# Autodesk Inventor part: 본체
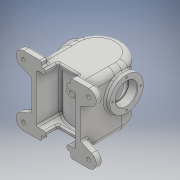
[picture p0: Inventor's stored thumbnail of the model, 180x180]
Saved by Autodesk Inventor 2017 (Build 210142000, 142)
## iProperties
Part Number: 본체
Material: 일반
Document SubType Name: Modeling
Designer: user
Density: 1 g/cm^3
Appearance: 기본값
Mass: 512.747 g
Surface Area: 1155.08 cm^2
Volume: 512.747 cm^3
Author: user
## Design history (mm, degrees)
sketch "스케치2"
  geometry: L1 (76, 0)-(76, -114); L2 (76, 0)-(121, 0); L3 (121, 0)-(121, -108); L4 (121, -108)-(104.5, -108); L5 (104.5, -108)-(104.5, -114); L6 (104.5, -114)-(92.5, -114); L7 (76, -9)-(112, -9); L8 (112, -9)-(112, -99); L9 (112, -99)-(92.5, -99); L10 (92.5, -99)-(92.5, -114); L11 (92.5, -114)-(76, -114); L12 (76, 0)-(76, -9); 1 further point
  constraints: 24 end point, 9 perpendicular, 2 horizontal, 1 collinear, 1 point on line, 1 vertical
  dimensions: "d3" = 76 distance from line of point (0, 0) L1; "d4" = 90 diameter of L3 L1; "d5" = 114 distance of L1.start L1.end; "d6" = 108 distance between parallel lines of L2 L4; "d7" = 57 diameter of L5 L1; "d8" = 0 distance from line of point (0, 0) L2; "d9" = 9 distance between parallel lines of L4 L9; "d10" = 9 distance between parallel lines of L2 L7; "d11" = 9 distance between parallel lines of L8 L3; "d12" = 33 diameter of L10 L1
revolve "회전1" sketch "스케치2" stored, may be unused: angle "d13" = 90 deg
node "작업 평면1"
sketch "스케치4"
  geometry: L1 (47.5, -114)-(104.5, -114) reference; C1 r 31 at (76, -40); 1 further point
  constraints: 1 centre point
  dimensions: "d15" = 62 diameter of C1; "d16" = 74 distance from line of L1 C1.centre; "d17" = 76 horizontal distance of point (0, 0) C1.centre
extrude "돌출1" join sketch "스케치4" stored distance "d18" = 10; taper "d19" = 0 deg
hole "구멍1" diameter "d22" = 35; stored, may be unused: countersink angle "d26" = 90 deg, drill point angle "d28" = 0 deg; dims "d20" = 10, "d21" = 10, "d23" = 6, "d24" = 40, "d25" = 16, "d27" = 8
node "작업 평면2"
sketch "스케치5"
  geometry: L1 (-28.5, -114)-(28.5, -114) reference; C1 r 7.5 at (0, -40); 1 further point
  constraints: 1 centre point, 1 vertical alignment
  dimensions: "d30" = 15 diameter of C1; "d31" = 74 distance from line of C1.centre L1
extrude "돌출2" join sketch "스케치5" stored distance "d32" = 10; taper "d33" = 0 deg
node "작업 평면3"
hole "구멍2" diameter "d37" = 5.188; stored, may be unused: countersink angle "d41" = 90 deg, drill point angle "d43" = 118 deg; dims "d35" = 10, "d36" = 10, "d38" = 12, "d39" = 40, "d40" = 16, "d42" = 16
sketch "스케치10" dims "d56" = 10, "d60" = 10
  geometry: L1 (74, 10)-(-74, 10); L2 (-74, 10)-(-74, -118); L3 (-74, -118)-(74, -118); L4 (74, -118)-(74, 10); L5 (-45, 0)-(45, 0) reference; L6 (60, 10)-(-60, 10); L7 (60, -118)-(-60, -118); L8 (74, -4)-(74, -104); L9 (-74, -4)-(-74, -104); A1 r 14 centre (60, -4) between (60, 10) and (74, -4); A2 r 14 centre (-60, -4) between (-60, 10) and (-74, -4); A3 r 14 centre (60, -104) between (60, -118) and (74, -104); A4 r 14 centre (-60, -104) between (-60, -118) and (-74, -104); 1 further point
  constraints: 16 end point, 8 point on circle, 8 point on line, 4 centre point, 2 horizontal, 2 parallel, 1 perpendicular, 1 vertical, 6 other
  dimensions: "d44" = 128 distance between parallel lines of L3 L1; "d45" = 148 distance of L1.start L1.end; "d46" = 74 distance from line of point (0, 0) L4; "d47" = 10 distance between parallel lines of L5 L1; "d48" = 28 diameter of A1; "d49" = 60 horizontal distance of point (0, 0) A1.centre; "d50" = 14 distance from line of L1 A1.centre; "d53" = 120 distance of A1.centre A2.centre; "d63" = 100 distance of A1.centre A3.centre
extrude "돌출3" join sketch "스케치10" distance "d65" = 12; taper "d66" = 0 deg
sketch "스케치13"
  geometry: L1 (74, 104)-(74, 4) reference; L2 (60, -10)-(-60, -10) reference; L3 (-74, 4)-(-74, 104) reference; L4 (-60, 118)-(60, 118) reference; L5 (-45, 0)-(45, 0); L6 (45, 0)-(45, 108); L7 (45, 108)-(-45, 108); L8 (-45, 108)-(-45, 0); L9 (-36, 9)-(36, 9); L10 (36, 9)-(36, 99); L11 (36, 99)-(-36, 99); L12 (-36, 99)-(-36, 9); A1 r 14 centre (60, 4) between (60, -10) and (74, 4) reference; A2 r 14 centre (-60, 4) between (-74, 4) and (-60, -10) reference; A3 r 14 centre (-60, 104) between (-60, 118) and (-74, 104) reference; A4 r 14 centre (60, 104) between (74, 104) and (60, 118) reference; 1 further point
  constraints: 16 end point, 4 parallel, 2 perpendicular, 1 horizontal, 3 other
  dimensions: "d67" = 10 distance between parallel lines of L2 L5; "d68" = 45 distance from line of point (0, 0) L8; "d69" = 45 distance from line of L6 point (0, 0); "d70" = 10 distance between parallel lines of L4 L7; "d71" = 9 distance between parallel lines of L8 L12
  node "절단 모서리 투영2"
extrude "돌출4" join sketch "스케치13" stored distance "d72" = 12; taper "d73" = 0 deg
sketch "스케치14"
  geometry: L1 (-78, -64)-(50, -64) reference; L2 (50, -64)-(50, -76) reference; L3 (50, -76)-(-78, -76) reference; L4 (-78, -76)-(-78, -64) reference; C1 r 31 at (0, 0) reference; C2 r 20 at (0, 0) reference; 1 further point
hole "구멍3" sketch "스케치14" at (0, 0) diameter "d74" = 40; stored, may be unused: countersink angle "d78" = 90 deg, drill point angle "d80" = 0 deg; dims "d75" = 12, "d76" = 40, "d77" = 16, "d79" = 16
extrude "돌출5" cut sketch "스케치13" stored distance "d81" = 12; taper "d82" = 0 deg
fillet "모깎기1" dims "d83" = 12
sketch "스케치15"
  geometry: L1 (40, -23)-(80, -23); L2 (80, -23)-(80, 23); L3 (80, 23)-(40, 23); L4 (40, 23)-(40, -23); L5 (40, -23)-(80, 23); L6 (80, -23)-(40, 23); L7 (0, 0)-(120, 0) reference; 1 further point
  constraints: 12 end point, 2 midpoint, 2 parallel, 1 horizontal, 1 perpendicular
  dimensions: "d84" = 23 distance between parallel lines of L3 L7; "d85" = 40 distance of L1.start L1.end
extrude "돌출6" cut sketch "스케치15" stored distance "d86" = 12; taper "d87" = 0 deg
sketch "스케치16"
  geometry: L1 (80, 0)-(80, 12) reference; L2 (80, 12)-(120, 12) reference; L3 (120, 0)-(120, 12) reference; L4 (120, 0)-(80, 0) reference; L5 (40, 12)-(40, 0) reference; L6 (40, 0)-(0, 0) reference; L7 (0, 0)-(0, 12) reference; L8 (0, 12)-(40, 12) reference; L9 (33, -12)-(87, -12); L10 (87, -12)-(87, 12); L11 (87, 12)-(33, 12); L12 (33, 12)-(33, -12); L13 (33, -12)-(87, 12); L14 (87, -12)-(33, 12); L15 (15, 76)-(15, 12) reference; 1 further point
  constraints: 12 end point, 2 midpoint, 2 parallel, 1 horizontal, 1 perpendicular
  dimensions: "d88" = 12 distance from line of point (60, 0) L11; "d89" = 18 distance between parallel lines of L15 L12
extrude "돌출7" cut sketch "스케치16" stored distance "d90" = 12; taper "d91" = 0 deg
sketch "스케치17"
  geometry: L1 (-87, -12)-(-33, -12); L2 (-33, -12)-(-33, 12); L3 (-33, 12)-(-87, 12); L4 (-87, 12)-(-87, -12); L5 (-87, -12)-(-33, 12); L6 (-33, -12)-(-87, 12); L7 (-105, 62.696)-(-105, 12) reference; 1 further point
  constraints: 12 end point, 2 midpoint, 2 parallel, 1 horizontal, 1 perpendicular
  dimensions: "d92" = 12 distance from line of point (-60, 0) L3; "d93" = 18 distance between parallel lines of L7 L4
extrude "돌출8" cut sketch "스케치17" stored distance "d94" = 12; taper "d95" = 0 deg
sketch "스케치18"
  geometry: L1 (-33, 108)-(-27, 108) reference; L2 (-27, 118)-(-27, 108) reference; L3 (-60, 118)-(-27, 118) reference; L4 (-74, 4)-(-74, 104) reference; L5 (-27, -10)-(-60, -10) reference; L6 (-27, 0)-(-27, -10) reference; L7 (-20, 0)-(-27, 0) reference; L8 (-20, 9)-(-20, 0) reference; L9 (-36, 9)-(-20, 9) reference; L10 (-36, 99)-(-36, 9) reference; L11 (-20, 99)-(-36, 99) reference; L12 (-20, 108)-(-20, 99) reference; L13 (-27, 108)-(-20, 108) reference; L14 (-45, 12)-(-45, 96) reference; L15 (-27, 0)-(-33, 0) reference; L16 (74, 104)-(74, 4) reference; L17 (60, -10)-(27, -10) reference; L18 (27, -10)-(27, 0) reference; L19 (33, 0)-(27, 0) reference; L20 (45, 96)-(45, 12) reference; L21 (27, 108)-(33, 108) reference; L22 (20, 108)-(27, 108) reference; L23 (20, 99)-(20, 108) reference; L24 (36, 99)-(20, 99) reference; L25 (36, 9)-(36, 99) reference; L26 (20, 9)-(36, 9) reference; L27 (20, 0)-(20, 9) reference; L28 (27, 0)-(20, 0) reference; L29 (27, 118)-(60, 118) reference; L30 (27, 108)-(27, 118) reference; L31 (65.693, 91.21)-(45, 82); L32 (45, 96)-(45, 12) reference; L33 (45, 26)-(65.693, 16.79); L34 (74, 4)-(74, 104) reference; L35 (74, 104)-(74, 4); L36 (45, 82)-(45, 26); A1 r 12 centre (-33, 96) between (-33, 108) and (-45, 96) reference; A2 r 14 centre (-60, 104) between (-60, 118) and (-74, 104) reference; A3 r 14 centre (-60, 4) between (-74, 4) and (-60, -10) reference; A4 r 12 centre (-33, 12) between (-45, 12) and (-33, 0) reference; A5 r 14 centre (60, 4) between (60, -10) and (74, 4) reference; A6 r 12 centre (33, 12) between (33, 0) and (45, 12) reference; A7 r 12 centre (33, 96) between (45, 96) and (33, 108) reference; A8 r 14 centre (60, 104) between (74, 104) and (60, 118) reference; A9 r 14 centre (60, 104) between (65.693, 91.21) and (74, 104); A10 r 14 centre (60, 4) between (60, -10) and (74, 4); A11 r 14 centre (60, 104) between (60, 118) and (65.693, 91.21); A12 r 14 centre (60, 104) between (74, 104) and (60, 118); A13 r 14 centre (60, 4) between (65.693, 16.79) and (60, -10); A14 r 14 centre (60, 4) between (74, 4) and (65.693, 16.79); 1 further point
  constraints: 12 point on circle, 11 end point, 6 centre point, 4 tangent, 2 coincident, 2 collinear, 2 point on line
  dimensions: "d98" = 36 distance from line of L29 L31.end; "d99" = 36 distance from line of L33.start L17
extrude "돌출9" cut sketch "스케치18" stored distance "d100" = 12; taper "d101" = 0 deg
sketch "스케치19"
  geometry: L1 (-33, 108)-(-27, 108) reference; L2 (-27, 118)-(-27, 108) reference; L3 (-60, 118)-(-27, 118) reference; L4 (-45, 82)-(-65.693, 91.21) reference; L5 (-45, 26)-(-45, 82) reference; L6 (-65.693, 16.79)-(-45, 26) reference; L7 (-27, -10)-(-60, -10) reference; L8 (-27, 0)-(-27, -10) reference; L9 (-27, 0)-(-33, 0) reference; L10 (-45, 12)-(-45, 26) reference; L11 (-45, 82)-(-45, 96) reference; L12 (-27, 108)-(-20, 108) reference; L13 (-20, 108)-(-20, 99) reference; L14 (-20, 99)-(-36, 99) reference; L15 (-36, 99)-(-36, 9) reference; L16 (-36, 9)-(-20, 9) reference; L17 (-20, 9)-(-20, 0) reference; L18 (-20, 0)-(-27, 0) reference; L19 (45, 96)-(45, 82) reference; L20 (65.693, 91.21)-(45, 82) reference; L21 (27, 118)-(60, 118) reference; L22 (27, 108)-(27, 118) reference; L23 (20, 108)-(27, 108) reference; L24 (20, 99)-(20, 108) reference; L25 (36, 99)-(20, 99) reference; L26 (36, 9)-(36, 99) reference; L27 (20, 9)-(36, 9) reference; L28 (20, 0)-(20, 9) reference; L29 (27, 0)-(20, 0) reference; L30 (27, -10)-(27, 0) reference; L31 (60, -10)-(27, -10) reference; L32 (45, 26)-(65.693, 16.79) reference; L33 (45, 26)-(45, 12) reference; L34 (33, 0)-(27, 0) reference; L35 (27, 108)-(33, 108) reference; L36 (45, 82)-(45, 26) reference; A1 r 12 centre (-33, 96) between (-33, 108) and (-45, 96) reference; A2 r 14 centre (-60, 104) between (-60, 118) and (-65.693, 91.21) reference; A3 r 14 centre (-60, 4) between (-65.693, 16.79) and (-60, -10) reference; A4 r 12 centre (-33, 12) between (-45, 12) and (-33, 0) reference; A5 r 12 centre (33, 96) between (45, 96) and (33, 108) reference; A6 r 14 centre (60, 104) between (65.693, 91.21) and (60, 118) reference; A7 r 14 centre (60, 4) between (60, -10) and (65.693, 16.79) reference; A8 r 12 centre (33, 12) between (33, 0) and (45, 12) reference; 1 further point
hole "구멍4" sketch "스케치19" at (-60, 4), (60, 4), (60, 104), (-60, 104) diameter "d102" = 6.6; stored, may be unused: countersink angle "d106" = 90 deg, drill point angle "d108" = 0 deg; dims "d103" = 12, "d104" = 18, "d105" = 2, "d107" = 16
sketch "스케치20"
  geometry: C1 r 20 at (0, 0); C2 r 31 at (0, 0) reference; 1 further point
  constraints: 1 centre point, 1 concentric
  dimensions: "d109" = 40 diameter of C1
extrude "돌출10" join sketch "스케치20" distance "d110" = 18; taper "d111" = 0 deg
hole "구멍5" diameter "d114" = 35; stored, may be unused: countersink angle "d118" = 90 deg, drill point angle "d120" = 0 deg; dims "d112" = 10, "d113" = 10, "d115" = 12, "d116" = 40, "d117" = 16, "d119" = 16
fillet "모깎기2" dims "d121" = 0.3
sketch "스케치21" dims "d122" = 52
  geometry: L1 (0, 0)-(0, 26); C1 r 20 at (0, 0) reference; C2 r 17.5 at (0, 0) reference; 6 further points
  constraints: 2 coincident, 2 end point, 1 vertical, 1 vertical alignment, 7 other
  dimensions: "d125" = 360 deg dimension on point (0, 0) point (0, 26) (derived)
hole "구멍6" sketch "스케치21" at (0, 26), (-26, 0), (0, -26), (26, 0) diameter "d127" = 3.242; stored, may be unused: countersink angle "d131" = 90 deg, drill point angle "d133" = 118 deg; dims "d128" = 8, "d129" = 40, "d130" = 16, "d132" = 10
sketch "스케치22" dims "d134" = 46
  geometry: L1 (0, 0)-(0, -23); C1 r 28.5 at (0, 0) reference; 6 further points
  constraints: 2 end point, 1 coincident, 1 vertical, 1 vertical alignment, 8 other
  dimensions: "d137" = 360 deg dimension on point (0, 0) point (0, -23) (derived)
hole "구멍7" sketch "스케치22" at (0, -23), (23, 0), (0, 23), (-23, 0) diameter "d139" = 3.242; stored, may be unused: countersink angle "d143" = 90 deg, drill point angle "d145" = 118 deg; dims "d140" = 8, "d141" = 40, "d142" = 16, "d144" = 10
fillet "모깎기3" dims "d146" = 3
fillet "모깎기4" dims "d147" = 3
fillet "모깎기5" dims "d148" = 3
fillet "모깎기6" dims "d149" = 3
fillet "모깎기7" dims "d150" = 3
fillet "모깎기8" dims "d151" = 3
fillet "모깎기9" dims "d152" = 3
sketch "스케치24" dims "d115" = 12
  geometry: L1 (35.676, 38.002)-(84.324, 38.002); L2 (84.324, 38.002)-(84.324, 31.998); L3 (84.324, 31.998)-(35.676, 31.998); L4 (35.676, 31.998)-(35.676, 38.002); L5 (35.676, 35)-(84.324, 35); L6 (60, 38.002)-(60, 31.998); L7 (90, 0)-(120, 0) reference; 1 further point
  constraints: 4 end point, 4 midpoint, 1 vertical alignment, 2 other
  dimensions: "d153" = 35 distance between parallel lines of L7 L5
feature "엠보싱1" sketch "스케치24" dims "d154" = 0.5, "d155" = 0
chamfer "모따기1" distance "d156" = 1; stored, may be unused: second distance "d157" = 2, angle "d158" = 45 deg
fillet "모깎기10" dims "d159" = 3
node "솔리드1"
mirror "미러1"
mirror "미러2"
mirror "미러3"
mirror "미러4"
mirror "미러5"
node "절단 모서리 투영3"
node "절단 모서리 투영4"
node "절단 모서리 투영5"
node "절단 모서리 투영6"
other parameters: "d14" = 54, "d29" = 125, "d34" = -49
